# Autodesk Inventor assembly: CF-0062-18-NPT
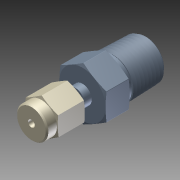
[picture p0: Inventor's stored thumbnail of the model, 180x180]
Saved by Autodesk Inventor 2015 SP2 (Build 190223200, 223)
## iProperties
Created: 2017-11
Part Number: CF-0062-18-NPT
Document SubType Name: Assembly
Designer: JN
Author: JN
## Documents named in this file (4)
- C:\Users\JN\Documents\CAD Drawings\The Sensor Connection\3D\CF\CF-0062-NPT\CF-0062-18-NPT.iam
- C:\Users\JN\Documents\CAD Drawings\The Sensor Connection\3D\CF\CF-0062-NPT\Imported Components\CF-0062-18-NPT Threaded Body\CF-0062-18-NPT Threaded Body.ipt
- C:\Users\JN\Documents\CAD Drawings\The Sensor Connection\3D\CF\CF-0062-NPT\Imported Components\CF-0062-18-NPT Cap\CF-0062-18-NPT Cap.ipt
- C:\Users\JN\Documents\CAD Drawings\The Sensor Connection\3D\CF\CF-0062-NPT\Imported Components\CF-0062-18-NPT Bottom Ferrule\CF-0062-18-NPT Bottom Ferrule.ipt
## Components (3 placed, 3 different names)
1. CF-0062-18-NPT Threaded Body:1 — Mate:1, Mate:2
2. CF-0062-18-NPT Cap:1
3. CF-0062-18-NPT Bottom Ferrule:1 — Mate:1, Mate:2
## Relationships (2: Mate 2)
- Mate:1: CF-0062-18-NPT Threaded Body:1 ↔ CF-0062-18-NPT Bottom Ferrule:1
- Mate:2: CF-0062-18-NPT Threaded Body:1 ↔ CF-0062-18-NPT Bottom Ferrule:1
